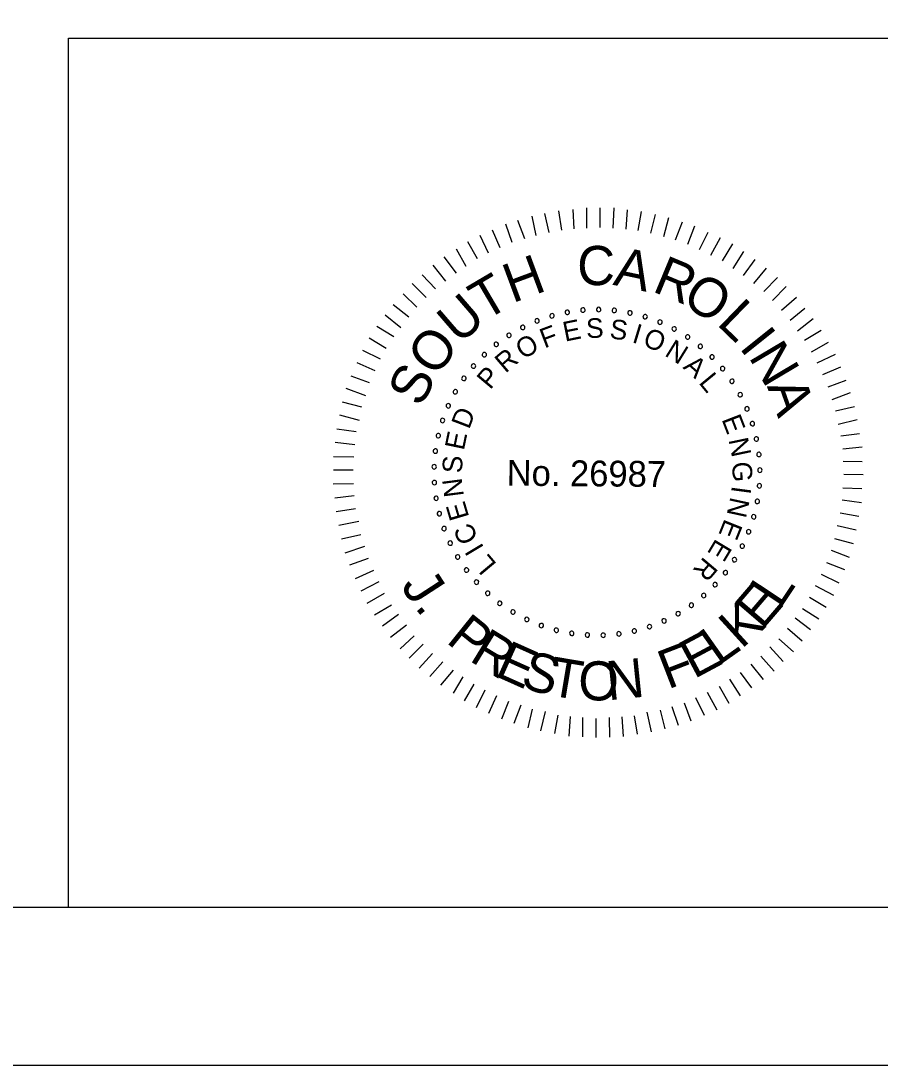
# Model space of a CAD drawing. Extents: x 1970675.2 to 1970711.3, y 796145.2 to 796167.2.
# Drawn here: x 1970697.72 to 1970700.44, y 796145.246 to 796148.551 of the extents above; entities that cross this region are included whole.
import ezdxf

# ---------------------------------------------------------------- set-up
doc = ezdxf.new("R2010")
doc.units = 0
for name, color, linetype in [('BR_BORDER LINES', 7, 'Continuous'), ('BR_TEXT', 7, 'Continuous'), ('Level 31', 7, 'Continuous')]:
    doc.layers.add(name, color=color, linetype=linetype)

msp = doc.modelspace()

# ---------------------------------------------------------------- linework, layer by layer
at = {"layer": 'BR_BORDER LINES'}
for p, q in [((1970697.8703, 796148.4964), (1970703.2355, 796148.4964)), ((1970697.8703, 796145.7463), (1970697.8703, 796148.4964)), ((1970677.0698, 796145.7463), (1970710.7358, 796145.7463))]:
    msp.add_line(p, q, dxfattribs=at)
at = {"layer": 'BR_TEXT'}
for p, q in [((1970699.432, 796147.8895), (1970699.4231, 796147.9504)), ((1970699.4715, 796147.8934), (1970699.4677, 796147.9544)), ((1970699.511, 796147.8957), (1970699.5116, 796147.96)), ((1970699.5531, 796147.8979), (1970699.5536, 796147.9597)), ((1970699.5951, 796147.895), (1970699.5974, 796147.9593)), ((1970699.6354, 796147.8921), (1970699.6402, 796147.9529)), ((1970699.674, 796147.8875), (1970699.6848, 796147.9483)), ((1970699.3151, 796147.8621), (1970699.2932, 796147.9198)), ((1970699.3512, 796147.8721), (1970699.338, 796147.9331)), ((1970699.3925, 796147.882), (1970699.3784, 796147.9414)), ((1970699.7143, 796147.8794), (1970699.7285, 796147.9385)), ((1970699.7554, 796147.8688), (1970699.7713, 796147.9295)), ((1970699.7922, 796147.8582), (1970699.8141, 796147.9155)), ((1970699.2368, 796147.8327), (1970699.2132, 796147.8887)), ((1970699.2755, 796147.8495), (1970699.2545, 796147.9081)), ((1970699.8316, 796147.8449), (1970699.8535, 796147.9031)), ((1970699.8675, 796147.8275), (1970699.8954, 796147.883)), ((1970699.1652, 796147.7981), (1970699.1348, 796147.8524)), ((1970699.1997, 796147.8158), (1970699.1735, 796147.8718)), ((1970699.9034, 796147.81), (1970699.9347, 796147.8656)), ((1970699.941, 796147.7917), (1970699.9732, 796147.8455)), ((1970699.1299, 796147.7744), (1970699.0994, 796147.8287)), ((1970699.9743, 796147.7674), (1970700.0082, 796147.8212)), ((1970699.0988, 796147.7532), (1970699.0597, 796147.8041)), ((1970700.0075, 796147.7457), (1970700.044, 796147.796)), ((1970699.0323, 796147.7031), (1970698.9906, 796147.748)), ((1970699.0651, 796147.7277), (1970699.0252, 796147.7778)), ((1970700.0399, 796147.7197), (1970700.0806, 796147.7691)), ((1970699.0029, 796147.6759), (1970698.9586, 796147.72)), ((1970700.0715, 796147.6945), (1970700.1147, 796147.7388)), ((1970698.9735, 796147.6452), (1970698.93, 796147.6876)), ((1970700.0995, 796147.6668), (1970700.1428, 796147.7102)), ((1970698.9483, 796147.6137), (1970698.8988, 796147.6527)), ((1970700.1276, 796147.6357), (1970700.1752, 796147.6774)), ((1970698.9223, 796147.5804), (1970698.8728, 796147.6203)), ((1970700.1548, 796147.6037), (1970700.2015, 796147.6419)), ((1970698.9006, 796147.5514), (1970698.8468, 796147.5845)), ((1970700.1786, 796147.57), (1970700.2278, 796147.6091)), ((1970700.2006, 796147.5407), (1970700.2532, 796147.5729)), ((1970698.8762, 796147.5147), (1970698.8225, 796147.5469)), ((1970700.2226, 796147.5036), (1970700.2761, 796147.5349)), ((1970698.8588, 796147.4805), (1970698.8024, 796147.5085)), ((1970700.2404, 796147.4691), (1970700.2981, 796147.4961)), ((1970698.8413, 796147.4438), (1970698.7841, 796147.4692)), ((1970700.2581, 796147.4321), (1970700.315, 796147.4565)), ((1970698.8238, 796147.4053), (1970698.7657, 796147.4272)), ((1970698.8115, 796147.3651), (1970698.7499, 796147.3879)), ((1970700.2749, 796147.3933), (1970700.3318, 796147.4143)), ((1970700.2883, 796147.3529), (1970700.346, 796147.3747)), ((1970698.7992, 796147.3291), (1970698.7384, 796147.3442)), ((1970700.2984, 796147.3168), (1970700.3585, 796147.3308)), ((1970698.792, 796147.2871), (1970698.7295, 796147.3031)), ((1970700.3066, 796147.2746), (1970700.3668, 796147.2896)), ((1970698.7814, 796147.2512), (1970698.7205, 796147.2594)), ((1970698.7768, 796147.21), (1970698.715, 796147.2174)), ((1970700.3149, 796147.2385), (1970700.3741, 796147.2458)), ((1970700.3214, 796147.1973), (1970700.3824, 796147.2036)), ((1970698.7738, 796147.1706), (1970698.7095, 796147.1711)), ((1970700.3228, 796147.1578), (1970700.3829, 796147.1573)), ((1970698.7718, 796147.1294), (1970698.7092, 796147.1299)), ((1970698.7732, 796147.0865), (1970698.7088, 796147.0853)), ((1970700.325, 796147.1166), (1970700.3859, 796147.1161)), ((1970700.3221, 796147.0737), (1970700.3822, 796147.0715)), ((1970698.7754, 796147.0478), (1970698.7136, 796147.0406)), ((1970700.32, 796147.0351), (1970700.3809, 796147.0269)), ((1970698.7794, 796147.0066), (1970698.7183, 796146.9977)), ((1970700.3129, 796146.994), (1970700.372, 796146.984)), ((1970698.7893, 796146.9671), (1970698.7266, 796146.9539)), ((1970700.3039, 796146.9546), (1970700.3639, 796146.9403)), ((1970698.7959, 796146.9249), (1970698.7348, 796146.9109)), ((1970698.8076, 796146.888), (1970698.7456, 796146.867)), ((1970700.295, 796146.9126), (1970700.3549, 796146.8975)), ((1970700.2844, 796146.8758), (1970700.3417, 796146.8538)), ((1970698.8192, 796146.8493), (1970698.7607, 796146.8283)), ((1970700.2704, 796146.8373), (1970700.3268, 796146.8153)), ((1970698.8361, 796146.8122), (1970698.7784, 796146.7852)), ((1970700.2529, 796146.8005), (1970700.3093, 796146.7726)), ((1970698.853, 796146.776), (1970698.7961, 796146.7465)), ((1970700.2346, 796146.7646), (1970700.2918, 796146.7341)), ((1970698.8698, 796146.739), (1970698.8155, 796146.7077)), ((1970700.2162, 796146.7279), (1970700.2692, 796146.6957)), ((1970698.8936, 796146.7019), (1970698.8392, 796146.6706)), ((1970700.1936, 796146.6911), (1970700.2457, 796146.659)), ((1970698.9148, 796146.6725), (1970698.8647, 796146.636)), ((1970700.1711, 796146.6622), (1970700.2197, 796146.6248)), ((1970698.9402, 796146.6388), (1970698.8901, 796146.5998)), ((1970700.1468, 796146.6289), (1970700.1928, 796146.589)), ((1970698.9649, 796146.6052), (1970698.9207, 796146.5643)), ((1970700.119, 796146.5956), (1970700.1659, 796146.5541)), ((1970698.9938, 796146.5792), (1970698.9488, 796146.5341)), ((1970700.0905, 796146.5701), (1970700.133, 796146.5243)), ((1970699.0227, 796146.5489), (1970698.9803, 796146.5029)), ((1970699.0552, 796146.5229), (1970699.0144, 796146.476)), ((1970700.0619, 796146.5403), (1970700.1044, 796146.4936)), ((1970699.0884, 796146.4969), (1970699.0485, 796146.4492)), ((1970700.03, 796146.5149), (1970700.0699, 796146.4673)), ((1970699.1191, 796146.4752), (1970699.0878, 796146.4231)), ((1970699.9635, 796146.4682), (1970699.9966, 796146.4156)), ((1970699.9972, 796146.4894), (1970700.0328, 796146.441)), ((1970699.1541, 796146.4526), (1970699.1228, 796146.3988)), ((1970699.1883, 796146.4326), (1970699.1612, 796146.377)), ((1970699.8919, 796146.4267), (1970699.9224, 796146.3707)), ((1970699.9299, 796146.4462), (1970699.9612, 796146.3918)), ((1970699.225, 796146.4151), (1970699.2005, 796146.3595)), ((1970699.2635, 796146.3976), (1970699.2416, 796146.3411)), ((1970699.8196, 796146.393), (1970699.8406, 796146.3362)), ((1970699.8558, 796146.4099), (1970699.8827, 796146.3539)), ((1970699.3029, 796146.3853), (1970699.2801, 796146.3271)), ((1970699.3388, 796146.3729), (1970699.3246, 796146.3139)), ((1970699.38, 796146.3658), (1970699.3648, 796146.3041)), ((1970699.7018, 796146.3631), (1970699.715, 796146.3012)), ((1970699.743, 796146.3696), (1970699.758, 796146.3103)), ((1970699.78, 796146.3813), (1970699.801, 796146.3228)), ((1970699.4193, 796146.3543), (1970699.4094, 796146.296)), ((1970699.4588, 796146.3497), (1970699.454, 796146.2879)), ((1970699.4982, 796146.3468), (1970699.4977, 796146.285)), ((1970699.5402, 796146.3438), (1970699.5397, 796146.2829)), ((1970699.5823, 796146.3461), (1970699.5835, 796146.2842)), ((1970699.6227, 796146.3483), (1970699.6264, 796146.2865)), ((1970699.6613, 796146.3523), (1970699.6712, 796146.2938))]:
    msp.add_line(p, q, dxfattribs=at)
for centre, start, end in [((1970699.4011, 796147.6179), 16.1422, 196.1422), ((1970699.4011, 796147.6179), 196.1422, 16.1422), ((1970699.4496, 796147.6294), 10.6038, 190.6038), ((1970699.4496, 796147.6294), 190.6038, 10.6038), ((1970699.499, 796147.6361), 5.0653, 185.0653), ((1970699.499, 796147.6361), 185.0653, 5.0653), ((1970699.5488, 796147.638), 359.5268, 179.5268), ((1970699.5488, 796147.638), 179.5268, 359.5268), ((1970699.5985, 796147.635), 173.9884, 353.9884), ((1970699.5985, 796147.635), 353.9884, 173.9884), ((1970699.6478, 796147.6273), 168.4499, 348.4499), ((1970699.6478, 796147.6273), 348.4499, 168.4499), ((1970699.696, 796147.6149), 162.9114, 342.9114), ((1970699.696, 796147.6149), 342.9114, 162.9114), ((1970699.3085, 796147.5813), 27.2191, 207.2191), ((1970699.3085, 796147.5813), 207.2191, 27.2191), ((1970699.3539, 796147.6019), 21.6807, 201.6807), ((1970699.3539, 796147.6019), 201.6807, 21.6807), ((1970699.7429, 796147.5979), 157.373, 337.373), ((1970699.7429, 796147.5979), 337.373, 157.373), ((1970699.7878, 796147.5764), 331.8345, 151.8345), ((1970699.2653, 796147.5565), 32.7576, 212.7576), ((1970699.2653, 796147.5565), 212.7576, 32.7576), ((1970699.7878, 796147.5764), 151.8345, 331.8345), ((1970699.8305, 796147.5507), 146.2961, 326.2961), ((1970699.8305, 796147.5507), 326.2961, 146.2961), ((1970699.2247, 796147.5276), 38.2961, 218.2961), ((1970699.2247, 796147.5276), 218.2961, 38.2961), ((1970699.8705, 796147.521), 140.7576, 320.7576), ((1970699.8705, 796147.521), 320.7576, 140.7576), ((1970699.1871, 796147.495), 43.8345, 223.8345), ((1970699.1871, 796147.495), 223.8345, 43.8345), ((1970699.9075, 796147.4876), 135.2191, 315.2191), ((1970699.9075, 796147.4876), 315.2191, 135.2191), ((1970699.1528, 796147.4588), 49.373, 229.373), ((1970699.1528, 796147.4588), 229.373, 49.373), ((1970699.9411, 796147.4508), 129.6807, 309.6807), ((1970699.9411, 796147.4508), 309.6807, 129.6807), ((1970699.1221, 796147.4196), 54.9114, 234.9114), ((1970699.1221, 796147.4196), 234.9114, 54.9114), ((1970699.9709, 796147.4109), 124.1422, 304.1422), ((1970699.9709, 796147.4109), 304.1422, 124.1422), ((1970699.0954, 796147.3775), 60.4499, 240.4499), ((1970699.0954, 796147.3775), 240.4499, 60.4499), ((1970699.9968, 796147.3683), 118.6038, 298.6038), ((1970699.9968, 796147.3683), 298.6038, 118.6038), ((1970699.0729, 796147.3331), 65.9884, 245.9884), ((1970699.0729, 796147.3331), 245.9884, 65.9884), ((1970700.0184, 796147.3234), 113.0653, 293.0653), ((1970700.0184, 796147.3234), 293.0653, 113.0653), ((1970699.0547, 796147.2867), 71.5268, 251.5268), ((1970699.0547, 796147.2867), 251.5268, 71.5268), ((1970700.0356, 796147.2766), 107.5268, 287.5268), ((1970700.0356, 796147.2766), 287.5268, 107.5268), ((1970699.0411, 796147.2387), 77.0653, 257.0653), ((1970699.0411, 796147.2387), 257.0653, 77.0653), ((1970700.0482, 796147.2284), 101.9884, 281.9884), ((1970700.0482, 796147.2284), 281.9884, 101.9884), ((1970699.0322, 796147.1897), 82.6038, 262.6038), ((1970699.0322, 796147.1897), 262.6038, 82.6038), ((1970700.0561, 796147.1792), 96.4499, 276.4499), ((1970700.0561, 796147.1792), 276.4499, 96.4499), ((1970699.0281, 796147.14), 88.1422, 268.1422), ((1970699.0281, 796147.14), 268.1422, 88.1422), ((1970700.0592, 796147.1295), 90.9114, 270.9114), ((1970700.0592, 796147.1295), 270.9114, 90.9114), ((1970699.0288, 796147.0902), 93.6807, 273.6807), ((1970699.0288, 796147.0902), 273.6807, 93.6807), ((1970700.0575, 796147.0797), 85.373, 265.373), ((1970700.0575, 796147.0797), 265.373, 85.373), ((1970699.0343, 796147.0407), 99.2191, 279.2191), ((1970699.0343, 796147.0407), 279.2191, 99.2191), ((1970700.0509, 796147.0303), 79.8345, 259.8345), ((1970700.0509, 796147.0303), 259.8345, 79.8345), ((1970699.0446, 796146.9919), 104.7576, 284.7576), ((1970699.0446, 796146.9919), 284.7576, 104.7576), ((1970700.0397, 796146.9817), 74.2961, 254.2961), ((1970700.0397, 796146.9817), 254.2961, 74.2961), ((1970699.0595, 796146.9444), 110.2961, 290.2961), ((1970699.0595, 796146.9444), 290.2961, 110.2961), ((1970700.0238, 796146.9345), 68.7576, 248.7576), ((1970700.0238, 796146.9345), 248.7576, 68.7576), ((1970699.0789, 796146.8985), 115.8345, 295.8345), ((1970699.0789, 796146.8985), 295.8345, 115.8345), ((1970700.0034, 796146.889), 63.2191, 243.2191), ((1970700.0034, 796146.889), 243.2191, 63.2191), ((1970699.1027, 796146.8547), 121.373, 301.373), ((1970699.1027, 796146.8547), 301.373, 121.373), ((1970699.1306, 796146.8134), 306.9114, 126.9114), ((1970699.9788, 796146.8457), 57.6807, 237.6807), ((1970699.9788, 796146.8457), 237.6807, 57.6807), ((1970699.1306, 796146.8134), 126.9114, 306.9114), ((1970699.9501, 796146.805), 52.1422, 232.1422), ((1970699.9501, 796146.805), 232.1422, 52.1422), ((1970699.1623, 796146.775), 132.4499, 312.4499), ((1970699.1623, 796146.775), 312.4499, 132.4499), ((1970699.9175, 796146.7672), 46.6038, 226.6038), ((1970699.9175, 796146.7672), 226.6038, 46.6038), ((1970699.1976, 796146.7398), 137.9884, 317.9884), ((1970699.1976, 796146.7398), 317.9884, 137.9884), ((1970699.8815, 796146.7328), 41.0653, 221.0653), ((1970699.8815, 796146.7328), 221.0653, 41.0653), ((1970699.2361, 796146.7082), 143.5268, 323.5268), ((1970699.2361, 796146.7082), 323.5268, 143.5268), ((1970699.8423, 796146.702), 35.5268, 215.5268), ((1970699.8423, 796146.702), 215.5268, 35.5268), ((1970699.2775, 796146.6805), 149.0653, 329.0653), ((1970699.2775, 796146.6805), 329.0653, 149.0653), ((1970699.3214, 796146.6569), 154.6038, 334.6038), ((1970699.3214, 796146.6569), 334.6038, 154.6038), ((1970699.756, 796146.6524), 24.4499, 204.4499), ((1970699.756, 796146.6524), 204.4499, 24.4499), ((1970699.8004, 796146.6751), 29.9884, 209.9884), ((1970699.8004, 796146.6751), 209.9884, 29.9884), ((1970699.3674, 796146.6376), 160.1422, 340.1422), ((1970699.3674, 796146.6376), 340.1422, 160.1422), ((1970699.415, 796146.6229), 165.6807, 345.6807), ((1970699.415, 796146.6229), 345.6807, 165.6807), ((1970699.6618, 796146.6203), 13.373, 193.373), ((1970699.6618, 796146.6203), 193.373, 13.373), ((1970699.7097, 796146.6341), 18.9114, 198.9114), ((1970699.7097, 796146.6341), 198.9114, 18.9114), ((1970699.4638, 796146.6128), 351.2191, 171.2191), ((1970699.4638, 796146.6128), 171.2191, 351.2191), ((1970699.5133, 796146.6075), 356.7576, 176.7576), ((1970699.5133, 796146.6075), 176.7576, 356.7576), ((1970699.5632, 796146.607), 2.2961, 182.2961), ((1970699.5632, 796146.607), 182.2961, 2.2961), ((1970699.6128, 796146.6113), 7.8345, 187.8345), ((1970699.6128, 796146.6113), 187.8345, 7.8345)]:
    msp.add_arc(centre, 0.00701, start, end, dxfattribs=at)
at = {"layer": 'Level 31'}
msp.add_lwpolyline([(1970675.2365, 796167.2463), (1970675.2365, 796145.2464), (1970711.2364, 796145.2464), (1970711.2364, 796167.2463)], dxfattribs=at)

# ---------------------------------------------------------------- texts
at = {"layer": 'BR_TEXT'}
for s, height, rotation, p in [('C', 0.1241, 359.5482, (1970699.4803, 796147.7155)), ('A', 0.1241, 348.1981, (1970699.5917, 796147.7163)), ('H', 0.1241, 20.3637, (1970699.2759, 796147.6572)), ('R', 0.1241, 337.4344, (1970699.715, 796147.6965)), ('T', 0.1241, 30.4992, (1970699.188, 796147.5997)), ('O', 0.1239, 326.5869, (1970699.8072, 796147.6597)), ('U', 0.1241, 40.8022, (1970699.1068, 796147.525)), ('L', 0.1241, 315.9488, (1970699.9198, 796147.5919)), ('F', 0.0622, 20.6127, (1970699.3772, 796147.5143)), ('E', 0.0622, 11.4103, (1970699.4423, 796147.536)), ('S', 0.0622, 2.208, (1970699.5102, 796147.547)), ('S', 0.0622, 352.6608, (1970699.5814, 796147.5468)), ('I', 0.0622, 343.1136, (1970699.6517, 796147.5348)), ('I', 0.1241, 308.6613, (1970699.9912, 796147.5176)), ('O', 0.1241, 52.0267, (1970699.0323, 796147.421)), ('O', 0.0622, 30.8477, (1970699.3098, 796147.4783)), ('O', 0.0622, 338.4392, (1970699.6851, 796147.5247)), ('N', 0.0622, 328.2042, (1970699.7547, 796147.4933)), ('N', 0.1241, 300.7037, (1970700.0218, 796147.4883)), ('R', 0.0622, 40.3949, (1970699.2537, 796147.4344)), ('A', 0.0622, 318.657, (1970699.8137, 796147.4532)), ('S', 0.1239, 63.2511, (1970698.9869, 796147.3254)), ('P', 0.0622, 49.9421, (1970699.2056, 796147.3818)), ('L', 0.0622, 309.4546, (1970699.8635, 796147.4059)), ('A', 0.1241, 289.4792, (1970700.081, 796147.3952)), ('D', 0.0622, 69.0364, (1970699.1386, 796147.2566)), ('E', 0.0622, 291.049, (1970699.9373, 796147.2906)), ('E', 0.0622, 78.2388, (1970699.122, 796147.1899)), ('N', 0.0622, 281.8466, (1970699.9595, 796147.2256)), ('S', 0.0622, 87.786, (1970699.1163, 796147.1189)), ('No. 26987', 0.08175, 359.5268, (1970699.2574, 796147.0804)), ('G', 0.0622, 272.2995, (1970699.9713, 796147.1553)), ('N', 0.0622, 97.3332, (1970699.1225, 796147.0479)), ('I', 0.0622, 262.4084, (1970699.9709, 796147.0814)), ('E', 0.0622, 106.5355, (1970699.1395, 796146.9813)), ('N', 0.0622, 257.7339, (1970699.9664, 796147.0468)), ('C', 0.0622, 116.4266, (1970699.1694, 796146.9138)), ('E', 0.0622, 248.1867, (1970699.9483, 796146.9779)), ('I', 0.0622, 121.1011, (1970699.1875, 796146.8839)), ('E', 0.0622, 238.9844, (1970699.9204, 796146.9151)), ('L', 0.0622, 129.9595, (1970699.2281, 796146.8318)), ('R', 0.0622, 229.782, (1970699.8827, 796146.8577)), ('J', 0.1236, 302.9559, (1970698.9202, 796146.7633)), ('E', 0.1236, 49.3639, (1970700.0662, 796146.6214)), ('L', 0.1236, 56.4247, (1970700.1237, 796146.6891)), ('K', 0.1236, 42.3031, (1970700.0009, 796146.5613)), ('.', 0.1236, 309.3974, (1970698.9643, 796146.6953)), ('P', 0.1236, 321.1035, (1970699.0627, 796146.5861)), ('R', 0.1236, 328.5359, (1970699.136, 796146.528)), ('E', 0.1236, 28.1814, (1970699.8506, 796146.4673)), ('L', 0.1236, 35.2422, (1970699.9286, 796146.5097)), ('E', 0.1236, 335.9684, (1970699.2161, 796146.4799)), ('F', 0.1236, 21.1206, (1970699.7679, 796146.4348)), ('S', 0.1236, 343.0292, (1970699.2974, 796146.4442)), ('T', 0.1236, 350.4617, (1970699.3871, 796146.4177)), ('O', 0.1236, 358.1419, (1970699.4825, 796146.4028)), ('N', 0.1236, 5.8221, (1970699.579, 796146.4007))]:
    msp.add_text(s, height=height, rotation=rotation, dxfattribs=at).set_placement(p)

doc.saveas('drawing.dxf')
